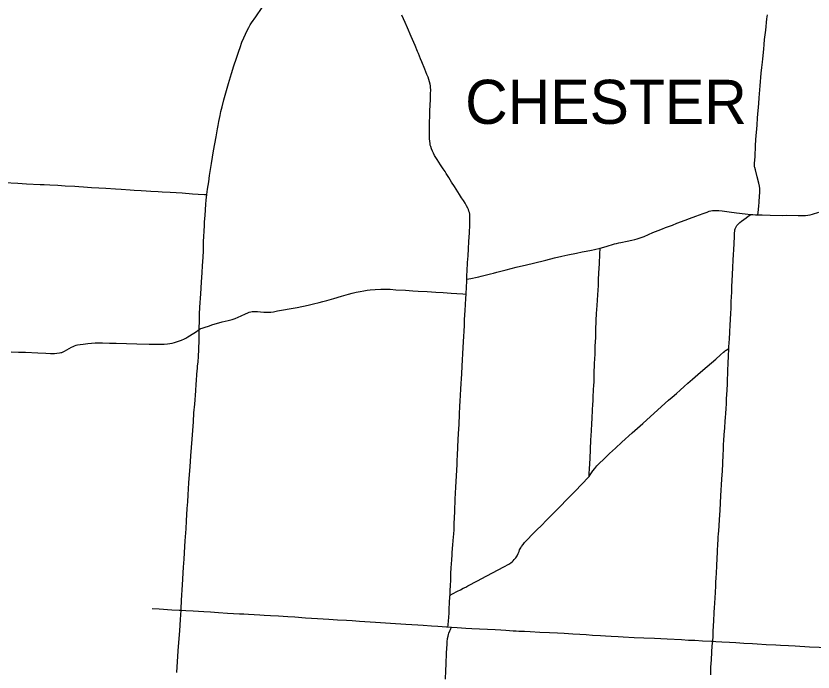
# Model space of a CAD drawing. Extents: x 1815539 to 1947826, y 273303 to 993194.
# Drawn here: x 1909861 to 1926135, y 885394 to 898782 of the extents above; entities that cross this region are included whole.
import ezdxf

# ---------------------------------------------------------------- set-up
doc = ezdxf.new("R2010")
doc.units = 0
for name, color, linetype in [('GM_X_County_Road', 7, 'Continuous'), ('GM_X_State_Route', 7, 'Continuous'), ('GM_X_Township_Road', 7, 'Continuous'), ('GM_X_Township_Text', 7, 'Continuous')]:
    doc.layers.add(name, color=color, linetype=linetype)

msp = doc.modelspace()

# ---------------------------------------------------------------- linework, layer by layer
at = {"layer": 'GM_X_County_Road'}
for points in [[(1925011, 894725), (1925015, 894769), (1925026, 894899), (1925033, 894980), (1925045, 895111), (1925049, 895176), (1925049, 895225), (1925047, 895258), (1925040, 895307), (1925026, 895371), (1924994, 895498), (1924957, 895641), (1924946, 895688), (1924943, 895705), (1924940, 895737), (1924941, 895770), (1924950, 895917), (1924962, 896129), (1924970, 896259), (1924992, 896553), (1925002, 896700), (1925026, 896994), (1925035, 897109), (1925054, 897353), (1925079, 897614), (1925089, 897728), (1925101, 897842), (1925108, 897908), (1925127, 898103), (1925137, 898201), (1925147, 898299), (1925157, 898396), (1925168, 898494), (1925193, 898722), (1925202, 898803)], [(1909620, 895383), (1909899, 895368), (1910079, 895359), (1910358, 895345), (1910439, 895341), (1910554, 895335), (1910718, 895326), (1910865, 895317), (1911062, 895306), (1911144, 895301), (1911242, 895295), (1911405, 895285), (1911552, 895278), (1911699, 895268), (1911896, 895256), (1912010, 895247), (1912190, 895235), (1912272, 895230), (1912419, 895221), (1912518, 895214), (1912616, 895208), (1912763, 895200), (1912845, 895196), (1913009, 895186), (1913254, 895170), (1913467, 895155), (1913581, 895147), (1913713, 895139), (1913758, 895138)], [(1921788, 894045), (1921909, 894079), (1922082, 894132), (1922120, 894142), (1922167, 894151), (1922210, 894159), (1922339, 894185), (1922436, 894205), (1922499, 894221), (1922546, 894235), (1922624, 894262), (1922685, 894285), (1922867, 894361), (1922973, 894405), (1923064, 894440), (1923125, 894464), (1923263, 894516), (1923356, 894551), (1923524, 894615), (1923616, 894650), (1923739, 894696), (1923893, 894753), (1923970, 894781), (1924017, 894796), (1924048, 894804), (1924081, 894810), (1924113, 894813), (1924163, 894815), (1924212, 894812), (1924277, 894805), (1924423, 894784), (1924570, 894765), (1924749, 894744), (1924863, 894733)], [(1925011, 894725), (1925093, 894722), (1925257, 894718), (1925503, 894713), (1925601, 894714), (1925831, 894710), (1925929, 894710), (1925979, 894713), (1926027, 894718), (1926076, 894727), (1926124, 894738), (1926250, 894775)], [(1924863, 894733), (1924904, 894730), (1924962, 894727), (1925011, 894725)], [(1919066, 893408), (1919150, 893423), (1919278, 893452), (1919310, 893460), (1919358, 893471), (1919438, 893491), (1919549, 893519), (1919613, 893536), (1919677, 893552), (1919868, 893601), (1920075, 893654), (1920282, 893704), (1920426, 893739), (1920681, 893801), (1920857, 893844), (1921009, 893882), (1921129, 893906), (1921306, 893944), (1921419, 893967), (1921500, 893980), (1921613, 894003), (1921674, 894017), (1921788, 894045)], [(1919051, 893107), (1919054, 893152), (1919057, 893206), (1919066, 893408)], [(1913604, 892383), (1913623, 892395), (1913639, 892402), (1913664, 892411), (1913727, 892430), (1913790, 892451), (1913881, 892483), (1913959, 892506), (1914070, 892537), (1914197, 892569), (1914276, 892590), (1914338, 892611), (1914400, 892635), (1914460, 892661), (1914548, 892704), (1914592, 892724), (1914623, 892735), (1914654, 892744), (1914685, 892750), (1914718, 892753), (1914750, 892753), (1914776, 892752), (1914791, 892751), (1914854, 892745), (1914920, 892738), (1914969, 892735), (1915019, 892736), (1915068, 892740), (1915117, 892747), (1915198, 892762), (1915326, 892787), (1915439, 892807), (1915600, 892836), (1915825, 892883), (1915937, 892907), (1916049, 892935), (1916128, 892956), (1916207, 892978), (1916349, 893018), (1916507, 893061), (1916648, 893102), (1916727, 893124), (1916806, 893144), (1916886, 893161), (1916966, 893175), (1917031, 893184), (1917096, 893191), (1917194, 893199), (1917308, 893206), (1917373, 893208), (1917422, 893207), (1917504, 893204), (1917618, 893196), (1917814, 893184), (1917962, 893176), (1918076, 893167), (1918256, 893157), (1918436, 893146), (1918583, 893137), (1918746, 893126), (1918861, 893120), (1918987, 893111), (1919051, 893107)], [(1913231, 886656), (1913331, 886648), (1913478, 886640), (1913585, 886634), (1913696, 886629), (1913835, 886620), (1913999, 886610), (1914177, 886598), (1914303, 886590), (1914428, 886584), (1914517, 886579), (1914609, 886574), (1914725, 886568), (1914839, 886562), (1914927, 886557), (1915059, 886551), (1915219, 886543), (1915415, 886527), (1915553, 886518), (1915772, 886503), (1916017, 886488), (1916247, 886473), (1916427, 886460), (1916607, 886449), (1916728, 886443), (1916876, 886433), (1917203, 886411), (1917507, 886391), (1917818, 886371), (1918064, 886355), (1918178, 886347), (1918342, 886336), (1918473, 886327), (1918653, 886315), (1918679, 886314)], [(1918679, 886314), (1918684, 886314), (1918751, 886310)], [(1918751, 886310), (1918868, 886303), (1919049, 886291), (1919170, 886285), (1919324, 886276), (1919486, 886268), (1919645, 886259), (1919758, 886253), (1919862, 886247), (1920014, 886238), (1920076, 886236), (1920128, 886231), (1920243, 886225), (1920357, 886220), (1920554, 886209), (1920751, 886202), (1920919, 886192), (1921054, 886185), (1921229, 886172), (1921372, 886165), (1921503, 886157), (1921634, 886148), (1921798, 886139), (1921896, 886132), (1922010, 886127), (1922158, 886119), (1922256, 886114), (1922485, 886102), (1922682, 886093), (1922895, 886083), (1923157, 886069), (1923449, 886055), (1923595, 886047), (1923723, 886041), (1923876, 886034), (1924062, 886022), (1924086, 886021)], [(1924086, 886021), (1924152, 886017), (1924272, 886010), (1924432, 886001), (1924559, 885995), (1924725, 885985), (1924898, 885976), (1924992, 885971), (1925178, 885959), (1925374, 885950), (1925473, 885944), (1925636, 885935), (1925767, 885928), (1926060, 885911), (1926257, 885899), (1926486, 885887), (1926601, 885879), (1926765, 885870), (1926812, 885867)]]:
    msp.add_lwpolyline(points, dxfattribs=at)
at = {"layer": 'GM_X_State_Route'}
msp.add_lwpolyline([(1913147, 885387), (1913176, 885829), (1913193, 886075), (1913204, 886238), (1913220, 886467), (1913231, 886656), (1913232, 886680), (1913243, 886860), (1913263, 887171), (1913285, 887531), (1913294, 887695), (1913310, 887957), (1913317, 888072), (1913334, 888316), (1913344, 888480), (1913359, 888732), (1913368, 888864), (1913377, 889008), (1913394, 889255), (1913406, 889426), (1913416, 889584), (1913433, 889805), (1913459, 890148), (1913483, 890499), (1913496, 890682), (1913511, 890862), (1913531, 891129), (1913540, 891267), (1913547, 891341), (1913556, 891464), (1913562, 891542), (1913566, 891586), (1913571, 891635), (1913578, 891725), (1913585, 891836), (1913592, 891977), (1913599, 892173), (1913603, 892321), (1913604, 892383), (1913608, 892583), (1913612, 892698), (1913618, 892841), (1913637, 893111), (1913651, 893349), (1913665, 893549), (1913673, 893680), (1913681, 893860), (1913687, 893991), (1913690, 894090), (1913692, 894172), (1913697, 894286), (1913703, 894385), (1913710, 894516), (1913714, 894581), (1913721, 894712), (1913728, 894826), (1913737, 894941), (1913745, 895023), (1913758, 895138), (1913774, 895250), (1913796, 895396), (1913816, 895526), (1913854, 895769), (1913897, 896028), (1913921, 896174), (1913947, 896319), (1913976, 896481), (1913988, 896545), (1914002, 896626), (1914028, 896754), (1914046, 896834), (1914070, 896930), (1914108, 897072), (1914202, 897404), (1914262, 897608), (1914310, 897765), (1914361, 897921), (1914409, 898061), (1914437, 898138), (1914476, 898246), (1914513, 898337), (1914546, 898412), (1914582, 898486), (1914613, 898544), (1914646, 898601), (1914673, 898642), (1914757, 898764), (1914885, 898954)], dxfattribs=at)
at = {"layer": 'GM_X_Township_Road'}
for points in [[(1919066, 893408), (1919069, 893493), (1919073, 893574), (1919083, 893754), (1919091, 893885), (1919099, 894032), (1919108, 894179), (1919118, 894359), (1919126, 894523), (1919130, 894605), (1919130, 894654), (1919128, 894704), (1919125, 894737), (1919118, 894769), (1919109, 894801), (1919098, 894832), (1919085, 894862), (1919062, 894907), (1919030, 894963), (1918996, 895018), (1918961, 895071), (1918916, 895139), (1918881, 895193), (1918846, 895249), (1918812, 895304), (1918753, 895391), (1918697, 895487), (1918647, 895566), (1918621, 895607), (1918586, 895661), (1918532, 895743), (1918460, 895853), (1918409, 895937), (1918385, 895980), (1918364, 896024), (1918345, 896069), (1918329, 896115), (1918321, 896146), (1918315, 896178), (1918308, 896226), (1918304, 896275), (1918302, 896324), (1918303, 896439), (1918306, 896619), (1918310, 896733), (1918313, 896848), (1918317, 896962), (1918323, 897077), (1918327, 897192), (1918329, 897273), (1918328, 897323), (1918325, 897356), (1918319, 897388), (1918307, 897436), (1918293, 897484), (1918277, 897530), (1918253, 897591), (1918209, 897697), (1918146, 897848), (1918121, 897909), (1918078, 898015), (1918059, 898060), (1918009, 898181), (1917930, 898360), (1917853, 898541), (1917807, 898646), (1917741, 898796)], [(1924416, 891996), (1924418, 892031), (1924427, 892195), (1924435, 892326), (1924444, 892489), (1924448, 892571), (1924457, 892734), (1924460, 892800), (1924466, 892954), (1924474, 893143), (1924480, 893258), (1924492, 893503), (1924499, 893651), (1924507, 893798), (1924513, 893913), (1924517, 894011), (1924529, 894273), (1924532, 894355), (1924535, 894388), (1924541, 894420), (1924545, 894436), (1924550, 894452), (1924556, 894467), (1924563, 894481), (1924572, 894495), (1924581, 894509), (1924603, 894533), (1924639, 894567), (1924677, 894598), (1924770, 894666), (1924809, 894695), (1924863, 894733)], [(1921561, 889386), (1921563, 889414), (1921567, 889461), (1921570, 889527), (1921577, 889659), (1921582, 889747), (1921592, 889945), (1921601, 890125), (1921611, 890314), (1921618, 890465), (1921624, 890566), (1921634, 890742), (1921639, 890855), (1921643, 890926), (1921649, 891034), (1921653, 891117), (1921656, 891168), (1921659, 891235), (1921663, 891321), (1921668, 891477), (1921676, 891693), (1921684, 891883), (1921690, 892031), (1921695, 892145), (1921697, 892210), (1921700, 892324), (1921703, 892406), (1921707, 892535), (1921710, 892596), (1921710, 892612), (1921713, 892662), (1921716, 892709), (1921721, 892792), (1921727, 892873), (1921742, 893089), (1921752, 893279), (1921757, 893395), (1921763, 893540), (1921768, 893628), (1921774, 893731), (1921783, 893919), (1921788, 894045)], [(1918723, 886964), (1918728, 887060), (1918733, 887157), (1918737, 887272), (1918742, 887403), (1918747, 887518), (1918757, 887681), (1918764, 887789), (1918767, 887830), (1918781, 887991), (1918793, 888155), (1918798, 888210), (1918805, 888301), (1918809, 888374), (1918810, 888433), (1918813, 888531), (1918821, 888678), (1918831, 888924), (1918842, 889169), (1918853, 889399), (1918860, 889513), (1918866, 889627), (1918871, 889726), (1918874, 889808), (1918884, 889987), (1918893, 890134), (1918899, 890265), (1918908, 890445), (1918919, 890658), (1918927, 890822), (1918932, 890920), (1918946, 891165), (1918953, 891279), (1918960, 891377), (1918966, 891476), (1918974, 891639), (1918995, 892016), (1919006, 892245), (1919011, 892343), (1919016, 892474), (1919021, 892589), (1919032, 892769), (1919046, 893014), (1919051, 893107)], [(1909764, 891927), (1909912, 891924), (1910059, 891918), (1910305, 891906), (1910469, 891898), (1910567, 891895), (1910649, 891896), (1910699, 891899), (1910747, 891906), (1910779, 891913), (1910795, 891917), (1910826, 891929), (1910855, 891943), (1910899, 891966), (1910998, 892024), (1911027, 892039), (1911058, 892052), (1911089, 892062), (1911120, 892070), (1911169, 892079), (1911234, 892088), (1911332, 892098), (1911479, 892109), (1911561, 892112), (1911627, 892112), (1911774, 892108), (1911905, 892103), (1912331, 892090), (1912578, 892085), (1912692, 892083), (1912807, 892083), (1912889, 892085), (1912955, 892089), (1913003, 892095), (1913052, 892103), (1913099, 892116), (1913162, 892137), (1913238, 892166), (1913299, 892191), (1913328, 892206), (1913370, 892231), (1913495, 892310), (1913544, 892342), (1913582, 892368), (1913604, 892383)], [(1921561, 889386), (1921584, 889418), (1921641, 889498), (1921681, 889550), (1921723, 889600), (1921768, 889647), (1921862, 889740), (1921980, 889852), (1922099, 889965), (1922232, 890086), (1922439, 890272), (1922659, 890469), (1922964, 890743), (1923184, 890940), (1923258, 891005), (1923345, 891080), (1923419, 891145), (1923504, 891221), (1923578, 891286), (1923677, 891372), (1923839, 891511), (1923975, 891629), (1924148, 891780), (1924246, 891867), (1924308, 891921), (1924333, 891942), (1924346, 891952), (1924360, 891960), (1924416, 891996)], [(1924086, 886021), (1924088, 886044), (1924093, 886107), (1924098, 886221), (1924105, 886340), (1924111, 886440), (1924117, 886604), (1924123, 886715), (1924127, 886783), (1924129, 886815), (1924134, 886895), (1924142, 887031), (1924147, 887141), (1924152, 887223), (1924158, 887322), (1924161, 887403), (1924168, 887566), (1924183, 887845), (1924191, 888025), (1924195, 888074), (1924200, 888139), (1924207, 888220), (1924211, 888269), (1924219, 888383), (1924226, 888498), (1924238, 888695), (1924254, 888989), (1924274, 889333), (1924284, 889497), (1924292, 889644), (1924301, 889841), (1924305, 889923), (1924310, 890038), (1924314, 890119), (1924323, 890233), (1924334, 890379), (1924344, 890510), (1924350, 890591), (1924356, 890673), (1924361, 890771), (1924365, 890870), (1924370, 890968), (1924380, 891147), (1924386, 891278), (1924390, 891376), (1924392, 891475), (1924392, 891540), (1924399, 891704), (1924406, 891835), (1924416, 891996)], [(1918723, 886964), (1918774, 886989), (1918875, 887042), (1918938, 887073), (1918992, 887102), (1919044, 887129), (1919087, 887152), (1919144, 887183), (1919230, 887227), (1919298, 887264), (1919357, 887296), (1919821, 887540), (1919922, 887595), (1919964, 887620), (1919990, 887640), (1920014, 887662), (1920036, 887687), (1920065, 887726), (1920091, 887768), (1920113, 887812), (1920133, 887857), (1920145, 887887), (1920169, 887930), (1920186, 887958), (1920215, 887998), (1920246, 888036), (1920302, 888097), (1920403, 888200), (1920491, 888288), (1920595, 888393), (1920687, 888486), (1920791, 888590), (1920884, 888683), (1920976, 888776), (1921102, 888905), (1921171, 888975), (1921309, 889115), (1921388, 889198), (1921445, 889257), (1921524, 889340), (1921545, 889365), (1921561, 889386)], [(1918679, 886314), (1918683, 886344), (1918686, 886365), (1918693, 886430), (1918699, 886512), (1918703, 886595), (1918707, 886709), (1918711, 886779), (1918714, 886842), (1918719, 886902), (1918721, 886940), (1918723, 886964)], [(1912641, 886691), (1912785, 886682), (1913044, 886665), (1913195, 886658), (1913231, 886656)], [(1918630, 885247), (1918638, 885424), (1918644, 885555), (1918654, 885785), (1918662, 885965), (1918666, 886013), (1918675, 886078), (1918684, 886127), (1918691, 886158), (1918701, 886190), (1918719, 886235), (1918732, 886265), (1918738, 886279), (1918751, 886310)], [(1924048, 885335), (1924050, 885494), (1924060, 885642), (1924071, 885802), (1924078, 885928), (1924086, 886021)]]:
    msp.add_lwpolyline(points, dxfattribs=at)

# ---------------------------------------------------------------- texts
at = {"layer": 'GM_X_Township_Text'}
msp.add_text('CHESTER', height=900, rotation=0, dxfattribs=at).set_placement((1919032, 896580))

doc.saveas('drawing.dxf')
